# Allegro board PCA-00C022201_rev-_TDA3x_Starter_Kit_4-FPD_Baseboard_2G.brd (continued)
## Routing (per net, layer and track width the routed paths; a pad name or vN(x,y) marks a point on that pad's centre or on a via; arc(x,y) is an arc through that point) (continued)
RGMII1_RXCTL: length 17.3
  TOP w0.127: J14.132 v1(76.52,4.76) ; U48.7 v1(82.54,13.21)
  INNER1 w0.127: v1(76.52,4.76) 77.72,5.27 78.3,5.27 78.55,5.02 79.63,5.02 80.01,5.21 80.39,5.59 80.39,7.24 82.54,9.39 v1(82.54,13.21)
RGMII1_RXD0: length 17.2
  TOP w0.127: U48.3 v1(80.54,14.99) ; J14.143 v1(79.52,10.92)
  INNER1 w0.127: v1(79.52,10.92) 78.78,10.18 78.78,9.82 78.9,9.7 79.16,9.7 80.52,11.05 80.52,11.35 80.39,11.48 79.65,11.48 79.52,11.6 79.52,11.86 79.65,11.98 80.39,11.98 80.52,12.11 80.52,12.37 80.39,12.49 79.65,12.49 79.52,12.62 79.52,12.87 79.65,13 80.39,13 80.52,13.13 80.52,13.38 80.39,13.51 79.65,13.51 79.52,13.64 79.52,13.86 79.63,13.97 80.29,13.97 80.42,14.1 80.42,14.3 80.29,14.43 79.94,14.43 79.81,14.55 79.81,14.86 79.94,14.99 v1(80.54,14.99)
  BOTTOM w0.127: R205.2 79.89,14.99 v1(80.54,14.99)
RGMII1_RXD1: length 17.2
  TOP w0.127: U48.4 v1(81.04,15.75) ; v1(79.82,5.84) 79.02,5.04 J14.142
  INNER1 w0.127: v1(79.82,5.84) 79.31,5.33 78.8,5.33 78.23,5.91 78.23,6.48 78.97,7.21 78.97,8.86 81.04,10.93 v1(81.04,15.75)
  BOTTOM w0.127: R206.2 81.04,16.52 v1(81.04,15.75)
RGMII1_RXD2: length 17.2
  TOP w0.127: v1(79.44,8.51) 79.02,8.93 J14.141 ; U48.5 v1(81.54,14.99)
  INNER1 w0.127: v1(81.54,14.99) 82.04,14.99 82.3,15.24 82.61,15.24 82.74,15.11 82.74,14.86 81.54,13.66 81.54,10.8 81.28,10.55 81.28,10.37 81.55,10.1 81.55,9.92 81.37,9.74 81.19,9.74 80.92,10.01 80.75,10.01 80.57,9.83 80.57,9.65 80.96,9.25 80.96,9.08 80.78,8.9 80.6,8.9 80.21,9.29 80.03,9.29 79.85,9.11 79.85,8.93 80.24,8.54 80.24,8.36 79.76,7.87 79.54,7.87 79.44,7.97 v1(79.44,8.51)
  BOTTOM w0.127: R207.1 81.54,14.17 v1(81.54,14.99)
RGMII1_RXD3: length 17.2
  TOP w0.127: v1(79.06,5.84) 78.52,5.3 J14.140 ; U48.6 v1(82.04,15.75)
  INNER1 w0.127: v1(79.06,5.84) 79.88,6.67 79.88,7.37 82.04,9.52 82.04,13.52 83.82,15.3 83.82,15.81 83.5,16.13 82.42,16.13 v1(82.04,15.75)
RGMII1_TXC: length 40.5
  TOP w0.127: v1(82.17,33.02) 82.8,33.02 83.44,33.66 85.47,33.66 86.11,34.29 86.61,34.29 86.78,34.13 U9.29 ; J14.135 v1(77.52,8.7)
  INNER1 w0.127: v1(77.52,8.7) 77.52,13.29 77.09,13.72 77.09,16.45 79.88,19.24 79.88,19.65 79.45,20.09 79.45,20.27 79.63,20.44 79.81,20.44 80.36,19.89 80.54,19.89 80.72,20.07 80.72,20.25 79.78,21.19 79.78,21.36 79.96,21.54 80.14,21.54 81.08,20.61 81.26,20.61 81.44,20.79 81.44,20.97 80.5,21.9 80.5,22.08 80.68,22.26 80.86,22.26 81.64,21.49 81.82,21.49 82.17,21.84 v1(82.17,33.02)
RGMII1_TXCTL: length 40.5
  TOP w0.127: J14.138 v1(78.02,4.76) ; v1(86.36,29.53) 86.76,29.93 U9.37
  INNER1 w0.127: v1(86.36,29.53) 86.36,18.25 86.23,18.12 85.03,18.12 84.9,17.99 84.9,17.74 85.03,17.61 86.23,17.61 86.36,17.48 86.36,17.23 86.23,17.1 85.03,17.1 84.9,16.98 84.9,16.72 85.03,16.6 86.23,16.6 86.36,16.47 86.36,16.21 86.23,16.09 85.03,16.09 84.9,15.96 84.9,15.71 85.03,15.58 86.23,15.58 86.41,15.4 86.41,14.4 83.31,11.3 83.31,9.46 80.9,7.05 80.9,5.4 80.14,4.64 78.15,4.64 v1(78.02,4.76)
RGMII1_TXD0: length 40.4
  TOP w0.127: v1(81.53,34.16) 85.34,34.16 85.88,34.7 86.77,34.7 86.84,34.63 U9.28 ; v1(76.2,5.84) 77.02,5.02 J14.134
  INNER1 w0.127: v1(76.2,5.84) 76.2,7.87 74.68,9.4 74.68,17.91 81.03,24.26 81.03,33.66 v1(81.53,34.16)
RGMII1_TXD1: length 40.5
  TOP w0.127: v1(82.17,34.92) 82.68,35.43 85.6,35.43 85.91,35.13 U9.27 ; v1(77.03,5.84) 77.52,5.35 J14.136
  INNER1 w0.127: v1(82.17,34.92) 82.17,33.91 81.53,33.27 81.53,24 76.07,18.54 76.07,10.49 75.95,10.36 75.76,10.36 75.63,10.23 75.63,9.98 75.76,9.85 75.95,9.85 76.07,9.72 76.07,9.02 77.03,8.06 v1(77.03,5.84)
RGMII1_TXD2: length 40.5
  TOP w0.127: J14.137 v1(78.02,10.92) ; v1(82.8,36.32) 83.12,36.64 85.03,36.64 86.04,35.63 U9.26
  INNER1 w0.127: v1(78.02,10.92) 78.02,13.55 77.6,13.97 77.6,16.19 81.23,19.83 81.41,19.83 81.84,19.41 82.02,19.41 82.2,19.59 82.2,19.77 81.77,20.19 81.77,20.37 81.95,20.55 82.13,20.55 82.56,20.13 82.74,20.13 82.92,20.31 82.92,20.48 82.61,20.79 82.61,21.21 82.8,21.4 82.8,21.93 82.93,22.06 83.31,22.06 83.44,22.19 83.44,22.44 83.31,22.57 82.93,22.57 82.8,22.7 82.8,22.95 82.93,23.08 83.31,23.08 83.44,23.2 83.44,23.46 83.31,23.58 82.93,23.58 82.8,23.71 82.8,23.97 82.93,24.09 83.31,24.09 83.44,24.22 83.44,24.47 83.31,24.6 82.93,24.6 82.8,24.73 82.8,24.98 82.93,25.11 83.31,25.11 83.44,25.24 83.44,25.49 83.31,25.62 82.93,25.62 82.8,25.74 v1(82.8,36.32)
RGMII1_TXD3: length 40.5
  TOP w0.127: U9.25 86.3,36.13 85.22,37.21 v1(83.57,37.21) ; v1(78.52,11.56) J14.139
  INNER1 w0.127: v1(78.52,11.56) 78.52,13.81 78.11,14.22 78.11,15.94 78.99,16.82 79.17,16.82 79.47,16.53 79.65,16.53 79.82,16.71 79.82,16.89 79.53,17.18 79.53,17.36 79.71,17.54 79.89,17.54 80.18,17.25 80.36,17.25 80.54,17.42 80.54,17.6 80.25,17.9 80.25,18.08 80.45,18.29 83.06,18.29 84.2,19.43 84.2,25.65 83.57,26.29 83.57,29.14 83.69,29.27 83.82,29.27 83.95,29.39 83.95,29.65 83.82,29.77 83.69,29.77 83.57,29.9 83.57,30.16 83.69,30.28 83.82,30.28 83.95,30.41 83.95,30.66 83.82,30.79 83.69,30.79 83.57,30.92 83.57,31.17 83.69,31.3 83.82,31.3 83.95,31.43 83.95,31.68 83.82,31.81 83.69,31.81 83.57,31.93 83.57,32.19 83.69,32.31 83.82,32.31 83.95,32.44 83.95,32.7 83.82,32.82 83.69,32.82 83.57,32.95 83.57,33.2 83.69,33.33 83.82,33.33 83.95,33.46 83.95,33.71 83.82,33.84 83.69,33.84 83.57,33.97 v1(83.57,37.21)
RIN0_C_N: length 14
  BOTTOM w0.127: R67.2 6.67,16.83 C77.2 7.68,16.36 7.81,16.23 10.13,16.23 11.35,17.45 15.39,17.45 15.61,17.67 L19.1 L19.2 17.92,17.67 18.14,17.45 18.82,17.45 C75.1
RIN0_C_P: length 19.5
  TOP w0.127: J6.5 v1(3.68,15.88)
  BOTTOM w0.127: C73.1 18.82,17.09 18.14,17.09 17.92,16.87 L19.3 L19.4 15.61,16.87 15.39,17.09 11.5,17.09 10.28,15.88 v1(3.68,15.88)
  BOTTOM w0.381: L17.2 4.36,16.55 v1(3.68,15.88)
RIN0_N: length 11.3
  BOTTOM w0.127: C75.2 20.6,17.45 22.66,17.45 27.74,22.53 29.13,22.53 U6.51
RIN0_P: length 11.3
  BOTTOM w0.127: C73.2 20.6,17.09 22.81,17.09 27.89,22.17 29.13,22.17 U6.50
RIN1_C_N: length 14
  BOTTOM w0.127: C76.1 18.82,30.15 18.14,30.15 17.92,30.37 L20.2 L20.1 15.61,30.37 15.39,30.15 11.35,30.15 10.13,28.93 7.81,28.93 7.68,29.06 C78.2 6.67,29.53 R68.2
RIN1_C_P: length 19.5
  TOP w0.127: J7.5 v1(3.68,28.57)
  BOTTOM w0.127: C74.1 18.82,29.79 18.14,29.79 17.92,29.57 L20.3 L20.4 15.61,29.57 15.39,29.79 11.5,29.79 10.28,28.57 v1(3.68,28.57)
  BOTTOM w0.381: L18.2 4.36,29.25 v1(3.68,28.57)
RIN1_N: length 12.1
  BOTTOM w0.127: C76.2 20.6,30.15 21.29,30.15 22.23,29.21 22.23,28.57 26.77,24.03 29.13,24.03 U6.54
RIN1_P: length 12.1
  BOTTOM w0.127: U6.53 29.13,23.67 26.63,23.67 21.87,28.43 21.87,29.06 21.14,29.79 20.6,29.79 C74.2
RIN2_C_N: length 14
  BOTTOM w0.127: R75.2 6.67,42.23 C91.2 7.68,41.76 7.81,41.63 10.13,41.63 11.35,42.85 15.39,42.85 15.61,43.07 L29.1 L29.2 17.92,43.07 18.14,42.85 18.82,42.85 C89.1
RIN2_C_P: length 19.5
  TOP w0.127: J8.5 v1(3.68,41.27)
  BOTTOM w0.127: v1(3.68,41.27) 10.28,41.27 11.5,42.49 15.39,42.49 15.61,42.27 L29.4 L29.3 17.92,42.27 18.14,42.49 18.82,42.49 C87.1
  BOTTOM w0.381: L27.2 4.36,41.95 v1(3.68,41.27)
RIN2_N: length 21.3
  BOTTOM w0.127: C89.2 20.6,42.85 21.67,42.85 26.8,37.72 26.8,28.19 27.96,27.03 29.13,27.03 U6.60
RIN2_P: length 21.3
  BOTTOM w0.127: U6.59 29.13,26.67 27.82,26.67 26.44,28.05 26.44,37.57 21.52,42.49 20.6,42.49 C87.2
RIN3_C_N: length 14
  BOTTOM w0.127: R76.2 6.67,54.93 C92.2 7.68,54.46 7.81,54.33 10.13,54.33 11.35,55.55 15.39,55.55 15.61,55.77 L30.1 L30.2 17.92,55.77 18.14,55.55 18.82,55.55 C90.1
RIN3_C_P: length 19.5
  TOP w0.127: J9.5 v1(3.68,53.98)
  BOTTOM w0.127: C88.1 18.82,55.19 18.14,55.19 17.92,54.97 L30.3 L30.4 15.61,54.97 15.39,55.19 11.5,55.19 10.28,53.98 v1(3.68,53.98)
  BOTTOM w0.381: L28.2 4.36,54.65 v1(3.68,53.98)
RIN3_N: length 32.5
  BOTTOM w0.127: U6.63 29.13,28.53 28.19,28.53 27.88,28.84 27.88,29.53 28.04,29.69 28.04,38.76 27.05,39.75 27.05,50.16 21.67,55.55 20.6,55.55 C90.2
RIN3_P: length 32.5
  BOTTOM w0.127: U6.62 29.13,28.17 28.04,28.17 27.52,28.69 27.52,29.68 27.69,29.84 27.69,38.61 26.7,39.6 26.7,50.02 21.52,55.19 20.6,55.19 C88.2
RSTOUTN: length 65.6
  TOP w0.152: TP78.1 89.41,1.65 89.15,1.91 86.02,1.91 ; 86.02,1.91 85,0.89 33.78,0.89 31.37,3.3 29.84,3.3 29.07,4.07 U22.3 ; 86.02,1.91 J14.170
RTCK: length 47.7
  TOP w0.127: J14.179 v1(88.52,10.73)
  INNER2 w0.127: v1(63.39,21.18) 63.39,18.53 73.15,8.76 75.18,8.76 81.92,2.03 87.38,2.03 89.03,3.68 89.03,5.97 86.98,8.01 86.98,9.19 v1(88.52,10.73)
  BOTTOM w0.127: v1(63.39,21.18) 62.89,21.68 J13.7
RX_CLK: length 2.4
  TOP w0.127: R179.2 85.72,32.77 86.04,32.45 86.68,32.45 86.85,32.63 U9.32
RX_CTRL: length 2.4
  TOP w0.127: R174.2 87.76,28.45 88.56,29.25 U9.38
RX_D0: length 2.4
  TOP w0.127: U9.33 86.29,32.13 85.83,31.66 RN5.8
RX_D1: length 2.4
  TOP w0.127: U9.34 86.36,31.63 85.85,31.11 RN5.7
RX_D2: length 2.4
  TOP w0.127: RN5.6 85.98,30.61 86.5,31.13 U9.35
RX_D3: length 2.4
  TOP w0.127: U9.36 86.63,30.63 86.07,30.06 RN5.5
SD_DETECT: length 121.2
  TOP w0.152: U22.18 v1(23.41,6.68)
  INNER1 w0.152: v1(23.41,6.68) 22.73,6 22.73,3.56 24,2.29 25.27,2.29 25.78,2.79 28.32,2.79 28.96,2.16 30.35,2.16 31.11,2.92 48.39,2.92 50.04,4.57 51.69,4.57 53.85,6.73 56.52,6.73 63.25,13.46 67.5,13.46 76.83,22.8 76.83,32 86.11,41.27 88.9,41.27 89.41,41.78 94.74,41.78 96.52,43.56 96.52,55.31 95.76,56.07 v1(91.18,56.07)
  BOTTOM w0.152: R151.2 R158.2 v1(91.18,56.07)
SPI1_CS1/SPI3_CS1: length 85.5
  TOP w0.127: J14.162 v1(84.02,4.76)
  INNER2 w0.127: v1(69.22,49.47) 68.45,50.23 59.82,50.23 59.05,49.47 51.88,49.47 45.59,55.75 41.15,55.75 J27.10
  BOTTOM w0.127: v1(69.22,49.47) 69.22,35.05 73.28,30.99 73.28,17.46 78.42,12.32 79.12,12.32 84.02,7.42 v1(84.02,4.76)
SW_RX_CLK: length 14.5
  TOP w0.127: R179.1 83.63,32.77 80.54,29.67 U48.18
SW_RX_CTRL: length 14.5
  TOP w0.127: U48.13 83.04,21.32 84.33,22.61 84.33,23.08 84.45,23.21 84.8,23.21 84.92,23.33 84.92,23.59 84.8,23.72 84.45,23.72 84.33,23.84 84.33,24.1 84.45,24.22 84.8,24.22 84.92,24.35 84.92,24.6 84.8,24.73 84.45,24.73 84.33,24.86 84.33,26.92 83.82,27.43 83.82,28.96 84.14,29.27 85.15,29.27 85.41,29.02 85.41,28.64 85.6,28.45 R174.1
SW_RX_D0: length 14.4
  TOP w0.127: U48.17 81.04,22.66 81.16,22.79 81.28,22.79 81.41,22.92 81.41,23.17 81.28,23.3 81.16,23.3 81.04,23.42 81.04,23.68 81.16,23.8 81.28,23.8 81.41,23.93 81.41,24.19 81.28,24.31 81.16,24.31 81.04,24.44 81.04,29.48 83.22,31.66 RN5.1
SW_RX_D1: length 14.5
  TOP w0.127: U48.16 81.54,22.1 81.92,22.48 81.92,24.66 81.79,24.79 81.66,24.79 81.53,24.92 81.53,25.17 81.66,25.3 81.79,25.3 81.92,25.42 81.92,25.68 81.79,25.81 81.66,25.81 81.53,25.93 81.53,26.19 81.66,26.31 81.79,26.31 81.92,26.44 81.92,26.69 81.79,26.82 81.66,26.82 81.53,26.95 81.53,27.2 81.66,27.33 81.79,27.33 81.92,27.46 81.92,27.71 81.79,27.84 81.66,27.84 81.53,27.96 81.53,29.27 83.37,31.11 RN5.2
SW_RX_D2: length 14.6
  TOP w0.127: U48.15 82.04,21.84 82.42,22.23 82.42,23.12 82.55,23.25 82.68,23.25 82.8,23.38 82.8,23.63 82.68,23.76 82.55,23.76 82.42,23.89 82.42,24.14 82.55,24.27 82.68,24.27 82.8,24.39 82.8,24.65 82.68,24.77 82.55,24.77 82.42,24.9 82.42,25.16 82.55,25.28 82.68,25.28 82.8,25.41 82.8,25.66 82.68,25.79 82.55,25.79 82.42,25.92 82.42,26.17 82.55,26.3 82.68,26.3 82.8,26.43 82.8,26.68 82.68,26.81 82.55,26.81 82.42,26.93 82.42,27.19 82.55,27.31 82.68,27.31 82.8,27.44 82.8,27.7 82.68,27.82 82.55,27.82 82.42,27.95 82.42,28.32 82.3,28.45 82.17,28.45 82.04,28.58 82.04,29.02 83.63,30.61 RN5.3
SW_RX_D3: length 14.5
  TOP w0.127: RN5.4 83.78,30.06 83.31,29.59 83.31,29.19 83.19,29.07 82.96,29.07 82.83,28.94 82.83,28.69 82.96,28.56 83.19,28.56 83.31,28.43 83.31,26.91 83.44,26.78 83.69,26.78 83.82,26.65 83.82,26.4 83.69,26.27 83.44,26.27 83.31,26.15 83.31,25.89 83.44,25.76 83.69,25.76 83.82,25.64 83.82,25.38 83.69,25.26 83.44,25.26 83.31,25.13 83.31,24.88 83.44,24.75 83.69,24.75 83.82,24.62 83.82,24.37 83.69,24.24 83.44,24.24 83.31,24.11 83.31,23.86 83.44,23.73 83.69,23.73 83.82,23.61 83.82,23.35 83.69,23.22 83.49,23.22 83.31,23.05 83.31,22.35 82.54,21.58 U48.14
TCLK: length 37.2
  TOP w0.127: J14.180 v1(88.52,4.76)
  INNER2 w0.127: v1(64.39,21.18) 64.39,19.05 73.66,9.78 77.34,9.78 80.84,6.29 80.84,4.89 81.79,3.94 87.69,3.94 v1(88.52,4.76)
  BOTTOM w0.127: J13.3 63.89,21.68 v1(64.39,21.18)
TD_A_N: length 12.9
  TOP w0.127: U9.2 94.33,31.05 95.3,31.05 95.63,30.72 95.63,29.97 95.35,29.69 95.35,29.36 95.51,29.2 96.19,29.2 96.31,29.32 96.31,30.08 96.65,30.42 97.09,30.42 v1(97.24,30.57)
  BOTTOM w0.127: J24.10 102.11,30.1 101.9,29.89 101.09,29.89 100.97,30.02 100.97,30.78 100.63,31.11 98.87,31.11 98.18,30.42 97.4,30.42 v1(97.24,30.57)
TD_A_P: length 12.9
  TOP w0.127: U9.1 94.33,30.7 95.15,30.7 95.28,30.57 95.28,30.12 95,29.84 95,29.21 95.37,28.84 96.33,28.84 96.67,29.18 96.67,29.94 96.8,30.06 97.09,30.06 v1(97.24,29.91)
  BOTTOM w0.127: J24.11 102.11,29.34 101.91,29.54 100.94,29.54 100.61,29.87 100.61,30.63 100.48,30.76 99.02,30.76 98.33,30.06 97.4,30.06 v1(97.24,29.91)
TD_B_N: length 12.9
  TOP w0.127: v1(98.22,31.71) 98.07,31.86 98.07,32.2 97.72,32.55 94.33,32.55 U9.5
  BOTTOM w0.127: J24.5 104.65,30.23 104.32,30.56 103.86,30.56 102.54,31.88 99.19,31.88 98.89,32.18 98.2,32.18 98.07,32.05 98.07,31.86 v1(98.22,31.71)
TD_B_P: length 12.9
  TOP w0.127: v1(97.56,31.71) 97.72,31.86 97.72,32.06 97.58,32.2 94.33,32.2 U9.4
  BOTTOM w0.127: J24.4 104.65,31.24 104.32,30.91 104.01,30.91 102.69,32.23 99.34,32.23 99.03,32.54 98.05,32.54 97.72,32.2 97.72,31.86 v1(97.56,31.71)
TD_C_N: length 12.9
  TOP w0.127: U9.8 94.33,34.05 97.32,34.05 v1(97.47,34.21)
  BOTTOM w0.127: J24.2 104.65,35.24 104.38,34.97 103.52,34.97 103.19,34.64 103.19,33.63 103.06,33.5 101.67,33.5 101.39,33.78 100.6,33.78 100.32,33.5 99.85,33.5 99.3,34.05 97.62,34.05 v1(97.47,34.21)
TD_C_P: length 12.9
  TOP w0.127: v1(97.47,33.55) 97.32,33.7 94.33,33.7 U9.7
  BOTTOM w0.127: v1(97.47,33.55) 97.62,33.7 99.15,33.7 99.7,33.15 100.47,33.15 100.75,33.43 101.24,33.43 101.52,33.15 103.21,33.15 103.54,33.48 103.54,34.49 103.67,34.62 104.38,34.62 104.65,34.35 J24.3
TD_D_N: length 12.9
  TOP w0.127: v1(97.55,36.07) 97.71,35.92 97.71,35.35 97.58,35.22 97.03,35.22 96.9,35.34 96.9,36.22 96.57,36.55 95.91,36.55 95.57,36.22 95.57,35.68 95.45,35.55 94.33,35.55 U9.11
  BOTTOM w0.127: v1(97.55,36.07) 97.71,35.92 97.71,35.41 98.04,35.08 98.53,35.08 98.87,34.73 100.67,34.73 101,35.07 101,35.51 101.13,35.64 101.9,35.64 102.11,35.43 J24.9
TD_D_P: length 12.9
  TOP w0.127: U9.10 94.33,35.2 95.59,35.2 95.93,35.53 95.93,36.07 96.06,36.2 96.42,36.2 96.55,36.07 96.55,35.2 96.88,34.86 97.73,34.86 98.06,35.2 98.06,35.92 v1(98.21,36.07)
  BOTTOM w0.127: v1(98.21,36.07) 98.06,35.92 98.06,35.56 98.19,35.43 98.68,35.43 99.02,35.09 100.52,35.09 100.65,35.22 100.65,35.66 100.98,35.99 101.91,35.99 102.11,36.2 J24.8
TDI: length 36.7
  TOP w0.127: J14.174 v1(87.02,2.54)
  INNER2 w0.127: v1(87.02,2.54) 82.42,2.54 80.39,4.57 80.39,6.1 79.63,6.86 77.85,6.86 75.44,9.27 73.41,9.27 63.87,18.81 63.87,21.42 v1(63.39,21.89)
  BOTTOM w0.127: J13.5 v1(63.39,21.89)
TDO: length 40.6
  TOP w0.127: J14.176 v1(87.52,4.76)
  INNER2 w0.127: v1(87.52,4.76) 87.2,4.45 86.11,4.45 85.34,5.21 85.34,5.46 80.52,10.29 73.91,10.29 64.95,19.25 64.95,25.73 v1(63.63,27.05)
  BOTTOM w0.127: v1(63.63,27.05) 63.89,27.31 J13.4
TFP410_DKEN: length 2.3
  TOP w0.127: R137.2 100.75,58.71 100.25,58.21 U16.35
TFP410_HTPLG: length 2.7
  TOP w0.127: U16.9 97.75,44.79 v1(97.28,44.32)
  BOTTOM w0.127: R136.2 97.03,44.58 v1(97.28,44.32)
TFP410_MSEN: length 2.3
  TOP w0.127: R138.2 98.75,43.38 U16.11
TFP410_PDN: length 99.7
  TOP w0.127: U22.20 v1(23.37,5.37)
  INNER1 w0.127: v1(93.73,42.86) 93.19,42.32 89.19,42.32 88.65,41.78 85.98,41.78 76.33,32.13 76.33,22.99 67.25,13.91 63.06,13.91 56.39,7.24 53.59,7.24 51.44,5.08 49.85,5.08 48.13,3.37 29.02,3.37 28.32,4.06 26.29,4.06 25.02,2.79 24.26,2.79 23.37,3.68 v1(23.37,5.37)
  BOTTOM w0.127: v1(93.73,42.86) 95.95,42.86 96.33,43.24 R134.2
TFP410_TFADJ: length 2.8
  TOP w0.127: v1(105.16,48.9) 104.39,48.9 104.18,48.68 103.25,48.68
  BOTTOM w0.127: v1(105.16,48.9) R139.1
TMS: length 37.1
  TOP w0.127: v1(88.02,5.52) J14.178
  INNER2 w0.127: v1(64.39,27.64) 64.39,27.18 85.89,5.67 85.89,5.29 86.23,4.95 86.8,4.95 87.38,5.52 v1(88.02,5.52)
  BOTTOM w0.127: J13.2 v1(64.39,27.64)
TRSTN: length 56.7
  TOP w0.127: R110.2 61.65,26.84 v1(61.65,27.56) 61.65,28.34 R109.2 ; J14.177 88.02,8.88 v1(88.42,8.48)
  INNER2 w0.127: v1(61.65,27.56) 60.38,26.29 60.38,24.7 62.47,22.61 62.47,17.92 73.66,6.73 73.66,4.7 76.14,2.22 76.14,1.52 76.52,1.14 87.76,1.14 89.79,3.17 89.79,6.48 88.42,7.85 v1(88.42,8.48)
TRSTPD: length 3.5
  TOP w0.127: R111.1 R109.1 62.63,27.89 v1(62.89,27.62)
  BOTTOM w0.127: J13.8 v1(62.89,27.62)
TVDD: length 2.3
  TOP w0.203: 103.25,53.68 v1(104.4,53.68) ; 103.25,50.68 v1(104.39,50.68)
TVDD_HDMI_IN: length 3.5
  TOP w0.305: U44.5 v1(57.25,50.04) ; U44.11 v1(54.25,50.04) ; U44.8 v1(55.75,50.04)
TXC_N: length 18.4
  TOP w0.127: 103.25,49.68 103.32,49.75 105.88,49.75 108.11,51.98 108.7,51.98 109.02,51.66 U20.15 111.03,51.66 111.36,51.98 114.2,51.98 114.52,51.66 U20.24 116.53,51.66 116.85,51.98 118.4,51.98 118.85,52.43 119.97,52.43 J19.12
TXC_P: length 18.4
  TOP w0.127: 103.25,50.18 103.32,50.11 105.74,50.11 107.97,52.34 108.7,52.34 109.02,52.66 U20.13 111.03,52.66 111.36,52.34 114.2,52.34 114.52,52.66 U20.26 116.53,52.66 116.85,52.34 118.25,52.34 118.7,52.79 119.97,52.79 J19.11
TXD0_N: length 18.4
  TOP w0.127: 103.25,51.18 103.32,51.25 105.48,51.25 107.71,53.49 108.7,53.49 109.02,53.16 U20.12 111.03,53.16 111.36,53.49 114.2,53.49 114.52,53.16 U20.27 116.53,53.16 116.85,53.49 117.21,53.49 117.35,53.34 118.23,53.34 118.53,53.63 119.97,53.63 J19.9
TXD0_P: length 18.4
  TOP w0.127: 103.25,51.68 103.32,51.61 105.33,51.61 107.56,53.84 108.7,53.84 109.02,54.16 U20.10 111.03,54.16 111.36,53.84 114.2,53.84 114.52,54.16 U20.29 116.53,54.16 116.85,53.84 117.36,53.84 117.5,53.7 118.08,53.7 118.38,53.99 119.97,53.99 J19.8
TXD1_N: length 18.4
  TOP w0.127: J19.6 119.97,54.84 118.52,54.84 118.22,55.13 117.48,55.13 117.34,54.99 116.85,54.99 116.53,54.66 U20.30 114.52,54.66 114.2,54.99 111.36,54.99 111.03,54.66 U20.9 109.02,54.66 108.7,54.99 107.3,54.99 105.07,52.75 103.32,52.75 103.25,52.68
TXD1_P: length 18.4
  TOP w0.127: J19.5 119.97,55.19 118.67,55.19 118.37,55.49 117.34,55.49 117.19,55.34 116.85,55.34 116.53,55.66 U20.32 114.52,55.66 114.2,55.34 111.36,55.34 111.03,55.66 U20.7 109.02,55.66 108.7,55.34 107.16,55.34 104.93,53.11 103.32,53.11 103.25,53.18
TXD2_N: length 18.4
  TOP w0.127: 103.25,54.18 103.32,54.25 104.67,54.25 106.9,56.49 108.7,56.49 109.02,56.16 U20.6 111.03,56.16 111.36,56.49 114.2,56.49 114.52,56.16 U20.33 116.53,56.16 116.85,56.49 118.52,56.49 118.97,56.03 119.97,56.03 J19.3
TXD2_P: length 18.4
  TOP w0.127: J19.2 119.97,56.39 119.12,56.39 118.67,56.84 116.85,56.84 116.53,57.16 U20.35 114.52,57.16 114.2,56.84 111.36,56.84 111.03,57.16 U20.4 109.02,57.16 108.7,56.84 106.75,56.84 104.52,54.61 103.32,54.61 103.25,54.68
UART1_RXD/DCAN2_TX: length 85.1
  TOP w0.127: J14.117 68.02,8.95 68.83,8.13 v1(69.72,8.13)
  INNER1 w0.127: v1(45.59,52.2) 46.86,53.47 46.86,60.96 43.56,64.26 42.8,64.26 J27.3
  BOTTOM w0.127: v1(45.59,52.2) 46.35,51.44 46.35,40.77 44.83,39.24 44.83,35.69 46.99,33.53 66.17,33.53 70.17,29.53 70.17,8.57 v1(69.72,8.13)
UART1_TXD/DCAN2_RX: length 80.9
  TOP w0.127: J14.119 68.92,9.82 v1(70.61,8.13)
  INNER1 w0.127: v1(45.59,53.09) 45.59,58.93 J27.5
  BOTTOM w0.127: v1(45.59,53.09) 46.86,51.82 46.86,40.51 45.34,38.99 45.34,35.94 47.24,34.04 66.42,34.04 70.61,29.84 v1(70.61,8.13)
UART2_CTSN: length 116.9
  TOP w0.152: v1(67.31,2.48) 67.02,2.77 J14.114
  INNER2 w0.152: J27.6 36.7,58.93 36.7,47.62 39.5,44.83 39.5,40.77 41.27,38.99 41.27,33.78 44.7,30.35 44.7,16 51.94,8.76 51.94,3.68 53.09,2.54 63.88,2.54 64.77,1.65 66.48,1.65 v1(67.31,2.48)
  BOTTOM w0.152: v1(67.31,2.48) 67.88,1.91 69.09,1.91 69.85,2.67 86.11,2.67 87,3.56 91.44,3.56 92.84,2.16 R324.1 98.86,2.16 Q7.1
UART2_RTSN: length 114
  TOP w0.152: J14.112 v1(66.52,2.54)
  INNER2 w0.152: J27.8 37.97,57.66 37.97,48.13 41.66,44.45 41.66,39.5 41.91,39.24 41.91,35.98 45.15,32.75 45.15,19.11 52.45,11.81 52.45,3.94 53.34,3.05 64.07,3.05 65.09,2.03 66.01,2.03 v1(66.52,2.54)
  BOTTOM w0.152: v1(66.52,2.54) 67.15,3.17 85.85,3.17 86.74,4.06 91.69,4.06 92.84,2.92 R323.1 95.25,3.05 95.89,3.68 96.27,3.68 96.9,4.32 96.9,4.95 97.16,5.21 98.68,5.21 98.86,5.39 Q8.1
UART2_RXD: length 90.9
  TOP w0.152: v1(71.37,5.78) 70.68,5.08 68.45,5.08 68.02,4.64 J14.118
  INNER1 w0.152: J27.4 41.15,63.37 43.31,63.37 46.23,60.45 v1(46.23,53.85)
  BOTTOM w0.152: v1(71.37,5.78) 71.75,6.16 71.75,30.23 66.93,35.05 47.75,35.05 47.12,35.69 47.12,38.48 47.88,39.24 47.88,53.47 47.5,53.85 v1(46.23,53.85)
UART2_TXD: length 92.9
  TOP w0.152: v1(70.36,5.78) 68.39,5.78 67.52,4.91 J14.116
  INNER1 w0.152: v1(47.37,53.09) 47.37,61.72 43.18,65.91 41.15,65.91 J27.2
  BOTTOM w0.152: v1(70.36,5.78) 71.25,6.68 71.25,29.96 66.67,34.54 47.5,34.54 45.85,36.2 45.85,38.61 47.37,40.13 v1(47.37,53.09)
UART3_CTSN: length 90.4
  TOP w0.152: v1(45.34,45.21) 41.78,45.21 39.69,43.12 v1(34.61,43.12) ; J14.164 v1(84.52,5.46)
  INNER2 w0.152: v1(69.85,48.13) 66.8,45.09 63.37,45.09 61.66,46.8 55.37,46.8 54.61,46.04 50.74,46.04 49.91,45.21 v1(45.34,45.21)
  BOTTOM w0.152: v1(69.85,48.13) 69.85,35.18 73.79,31.24 73.79,17.72 78.68,12.83 79.38,12.83 84.52,7.68 v1(84.52,5.46) ; R104.2 v1(34.61,43.12)
UART3_RTSN: length 93.9
  TOP w0.152: J14.166 v1(85.02,4.76) ; v1(32.32,43.12) 34.29,45.09 37.01,45.09 39.29,47.37 v1(45.34,47.37)
  INNER2 w0.152: v1(70.48,48.77) 67.69,48.77 67.12,49.34 60.33,49.34 59.44,48.45 50.99,48.45 49.91,47.37 v1(45.34,47.37)
  BOTTOM w0.152: v1(70.48,48.77) 70.48,35.31 74.3,31.5 74.3,17.97 78.93,13.34 80.77,13.34 85.02,9.09 v1(85.02,4.76) ; R101.2 v1(32.32,43.12)
UART3_RXD_BOOT: length 90.7
  TOP w0.152: v1(36.51,43.81) 39.49,43.81 41.53,45.85 46.1,45.85 v1(48.51,48.26) ; J14.158 v1(83.02,4.76)
  INNER2 w0.152: v1(48.51,48.26) 49.91,48.26 50.61,48.96 59.25,48.96 60.07,49.78 67.63,49.78 v1(67.94,49.47)
  BOTTOM w0.152: v1(67.94,49.47) 67.94,34.8 72.26,30.48 72.26,11.18 73.91,9.53 80.39,9.53 83.02,6.9 v1(83.02,4.76) ; R105.2 v1(36.51,43.81)
UART3_TXD_BOOT: length 92.4
  TOP w0.152: v1(83.52,5.46) J14.160 ; v1(45.34,46.48) 41.15,46.48 39.12,44.45 34.8,44.45 v1(33.46,43.12)
  INNER2 w0.152: v1(68.58,48.13) 64.52,48.13 64.33,47.94 51.37,47.94 49.91,46.48 v1(45.34,46.48)
  BOTTOM w0.152: v1(68.58,48.13) 68.58,34.93 72.77,30.73 72.77,11.43 74.04,10.16 80.52,10.16 83.52,7.16 v1(83.52,5.46) ; R102.2 v1(33.46,43.12)
USB_CTS: length 1.3
  TOP w0.152: U47.15 33.14,54.3 R299.1
USB_DM: length 17
  TOP w0.135: J23.2 22.31,65.54 22.31,63.3 v1(22.5,63.11) ; v1(31.55,60.58) 31.74,60.39 31.74,59.44 31.63,59.33 U47.5
  BOTTOM w0.135: v1(31.55,60.58) 31.74,60.77 31.74,61.13 30.92,61.95 28.39,61.95 U49.5 28.15,61.95 27.64,61.95 27.15,62.43 26.79,62.43 U49.2 26.59,62.43 25.68,62.43 24.05,64.06 22.71,64.06 22.31,63.66 22.31,63.3 v1(22.5,63.11)
USB_DP: length 17.9
  TOP w0.135: U47.4 32.14,59.33 32.03,59.44 32.03,60.39 v1(32.22,60.58) ; v1(21.84,63.11) 22.03,63.3 22.03,65.54 J23.3
  BOTTOM w0.135: v1(32.22,60.58) 32.03,60.77 32.03,61.25 31.04,62.24 27.75,62.24 27.27,62.72 26.78,62.72 26.69,62.81 U49.3 26.58,62.72 25.8,62.72 24.17,64.35 22.59,64.35 22.03,63.78 22.03,63.3 v1(21.84,63.11)
USB_RTS: length 1.9
  TOP w0.152: R300.1 34.28,55.26 U47.16
USB_RXD: length 7.7
  TOP w0.152: v1(33.79,51.5) 34.29,51.5 35.18,52.39 35.18,55.75 34.53,56.4 U47.17
  BOTTOM w0.152: U38.11 v1(33.79,51.5)
USB_TXD: length 8.5
  TOP w0.152: U47.18 34.79,56.9 35.81,55.88 v1(35.81,52.07)
  BOTTOM w0.152: v1(35.81,52.07) 35.18,52.07 34.79,51.68 U38.13
VOUT1_CLK: length 98
  TOP w0.127: J14.51 v1(46.51,10.86) ; v1(90.49,51.18) 91.75,51.18 U16.57
  INNER1 w0.127: v1(46.51,10.86) 46.66,11.23 50.29,14.86 55.24,14.86 61.52,21.13 61.7,21.13 62.79,20.04 62.97,20.04 63.15,20.22 63.15,20.4 62.06,21.49 62.06,21.67 62.24,21.85 62.49,21.85 62.72,22.08 62.72,22.34 63.63,23.25 63.81,23.25 65.16,21.9 65.34,21.9 65.52,22.08 65.52,22.26 64.17,23.61 64.17,23.79 64.35,23.96 64.53,23.96 65.87,22.62 66.05,22.62 66.23,22.8 66.23,22.98 64.89,24.32 64.89,24.5 65.07,24.68 65.25,24.68 66.59,23.34 66.77,23.34 66.95,23.52 66.95,23.7 65.61,25.04 65.61,25.22 65.79,25.4 65.97,25.4 67.31,24.06 67.49,24.06 67.67,24.24 67.67,24.42 66.33,25.76 66.33,25.94 66.51,26.12 66.69,26.12 68.03,24.78 68.21,24.78 68.39,24.96 68.39,25.14 67.05,26.48 67.05,26.66 67.23,26.84 67.41,26.84 68.75,25.5 68.93,25.5 69.11,25.68 69.11,25.86 67.77,27.2 67.77,27.38 67.94,27.56 68.12,27.56 69.09,26.6 69.27,26.6 69.45,26.78 69.45,26.95 68.48,27.92 68.48,28.1 68.71,28.32 68.71,28.66 68.83,28.78 69.34,28.78 69.47,28.91 69.47,29.17 69.34,29.29 68.83,29.29 68.71,29.42 68.71,29.67 68.83,29.8 69.34,29.8 69.47,29.93 69.47,30.18 69.34,30.31 68.83,30.31 68.71,30.44 68.71,30.99 88.9,51.18 89.27,51.18 89.4,51.31 89.4,51.44 89.53,51.56 89.78,51.56 89.91,51.44 89.91,51.31 90.03,51.18 v1(90.49,51.18)
VOUT1_D0: length 93.5
  TOP w0.127: v1(90.49,48.18) U16.63 ; J14.43 44.51,8.95 44.7,8.76 49.34,8.76 50.48,7.62 v1(50.48,7.56)
  INNER1 w0.127: v1(90.49,48.18) 91.19,48.88 91.19,54.86 91.44,55.12 93.15,55.12 93.41,54.86 93.41,46.74 92.58,45.91 87.57,45.91 73.72,32.07 73.72,24.83 72.9,24 72.9,23.37 66.1,16.57 61.91,16.57 57.4,12.06 57.02,12.06 56.52,12.57 51.05,12.57 49.97,11.49 49.97,8.06 v1(50.48,7.56)
VOUT1_D1: length 93.9
  TOP w0.127: J14.41 44.01,8.82 44.37,8.46 48.69,8.46 v1(49.59,7.56) ; v1(89.66,48.68) U16.62
  INNER1 w0.127: v1(89.66,48.68) 89.66,48.13 90.11,47.69 90.87,47.69 91.63,48.45 91.63,54.42 91.82,54.61 92.77,54.61 92.96,54.42 92.96,47.18 92.14,46.35 87.33,46.35 73.28,32.3 73.28,25.02 72.39,24.13 72.39,23.5 65.91,17.02 61.72,17.02 57.4,12.7 57.02,12.7 56.77,12.95 50.93,12.95 49.59,11.62 v1(49.59,7.56)
VOUT1_D2: length 95.7
  TOP w0.127: v1(90.49,49.18) U16.61 ; v1(48.7,7.56) 48.11,8.15 44.09,8.15 43.51,8.73 J14.39
  INNER1 w0.127: v1(48.7,7.56) 49.15,8 49.15,11.68 50.8,13.34 57.4,13.34 61.53,17.46 65.09,17.46 65.45,17.83 65.63,17.83 65.77,17.69 65.95,17.69 66.13,17.87 66.13,18.05 65.99,18.19 65.99,18.37 66.17,18.55 66.35,18.55 66.49,18.41 66.67,18.41 66.85,18.59 66.85,18.77 66.71,18.91 66.71,19.09 66.89,19.27 67.07,19.27 67.21,19.13 67.39,19.13 67.57,19.31 67.57,19.49 67.43,19.63 67.43,19.81 67.61,19.99 67.79,19.99 67.93,19.85 68.11,19.85 68.29,20.03 68.29,20.21 68.15,20.35 68.15,20.53 68.33,20.7 68.51,20.7 68.65,20.57 68.83,20.57 69.01,20.75 69.01,20.93 68.87,21.06 68.87,21.24 69.05,21.42 69.23,21.42 69.37,21.29 69.55,21.29 69.73,21.47 69.73,21.65 69.59,21.78 69.59,21.96 69.77,22.14 69.95,22.14 70.08,22 70.26,22 70.44,22.18 70.44,22.36 70.31,22.5 70.31,22.68 70.49,22.86 70.67,22.86 70.8,22.72 70.98,22.72 71.16,22.9 71.16,23.08 71.03,23.22 71.03,23.4 71.21,23.58 71.38,23.58 71.52,23.44 71.7,23.44 71.88,23.62 71.88,23.8 71.74,23.94 71.74,24.12 72.83,25.21 72.83,32.58 87.06,46.8 91.63,46.8 92.52,47.69 92.52,52.32 92.39,52.45 92.2,52.45 92.08,52.32 92.08,48.2 91.12,47.24 89.92,47.24 89.09,48.07 89.09,48.83 89.44,49.18 v1(90.49,49.18)
VOUT1_D3: length 92.1
  TOP w0.127: v1(47.82,7.56) 47.52,7.85 43.84,7.85 43.01,8.68 J14.37 ; v1(89.66,49.68) U16.60
  INNER1 w0.127: v1(47.82,7.56) 48.64,8.38 48.64,11.68 50.67,13.72 57.15,13.72 61.34,17.91 62.01,17.91 62.14,18.03 62.14,18.54 62.26,18.67 62.52,18.67 62.64,18.54 62.64,18.03 62.77,17.91 63.02,17.91 63.15,18.03 63.15,18.54 63.28,18.67 63.53,18.67 63.66,18.54 63.66,18.03 63.79,17.91 64.14,17.91 64.32,18.09 64.32,18.27 64.21,18.37 64.21,18.55 64.39,18.73 64.57,18.73 65.06,18.25 65.24,18.25 65.51,18.52 65.51,18.7 65.37,18.83 65.37,19.01 65.56,19.2 65.74,19.2 65.87,19.06 66.05,19.06 66.23,19.24 66.23,19.42 66.1,19.56 66.1,19.74 66.28,19.92 66.46,19.92 66.59,19.78 66.77,19.78 66.95,19.96 66.95,20.14 66.81,20.28 66.81,20.46 66.99,20.64 67.17,20.64 67.31,20.5 67.49,20.5 67.67,20.68 67.67,20.86 67.53,21 67.53,21.18 67.71,21.36 67.89,21.36 68.03,21.22 68.21,21.22 68.39,21.4 68.39,21.58 68.25,21.72 68.25,21.9 68.43,22.08 68.61,22.08 68.75,21.94 68.93,21.94 69.11,22.12 69.11,22.3 68.97,22.44 68.97,22.62 69.15,22.8 69.33,22.8 69.47,22.66 69.65,22.66 69.83,22.84 69.83,23.02 69.69,23.15 69.69,23.33 69.87,23.51 70.05,23.51 70.19,23.38 70.37,23.38 70.55,23.56 70.55,23.74 70.41,23.87 70.41,24.05 70.59,24.23 70.77,24.23 70.91,24.1 71.09,24.1 71.34,24.35 71.34,24.53 71.2,24.66 71.2,24.84 71.38,25.02 71.56,25.02 71.7,24.89 71.88,24.89 72.26,25.27 72.26,25.5 72.13,25.63 71.88,25.63 71.75,25.76 71.75,26.01 71.88,26.14 72.26,26.14 72.39,26.27 72.39,26.52 72.26,26.65 71.88,26.65 71.75,26.77 71.75,27.03 71.88,27.16 72.26,27.16 72.39,27.28 72.39,27.54 72.26,27.66 71.88,27.66 71.75,27.79 71.75,28.04 71.88,28.17 72.26,28.17 72.39,28.3 72.39,28.55 72.26,28.68 71.88,28.68 71.75,28.81 71.75,29.06 71.88,29.19 72.26,29.19 72.39,29.31 72.39,29.57 72.26,29.7 71.88,29.7 71.75,29.82 71.75,30.08 71.88,30.2 72.26,30.2 72.39,30.33 72.39,30.58 72.26,30.71 71.88,30.71 71.75,30.84 71.75,31.09 71.88,31.22 72.26,31.22 72.39,31.35 72.39,31.6 72.26,31.73 71.88,31.73 71.75,31.85 71.75,32.13 86.87,47.24 87.18,47.24 87.3,47.37 87.3,47.62 87.43,47.75 87.68,47.75 87.81,47.62 87.81,47.37 87.94,47.24 88.75,47.24 88.87,47.37 88.87,47.65 88.5,48.03 88.14,48.03 88.01,48.15 88.01,48.41 88.14,48.54 88.52,48.54 88.65,48.66 88.65,49.02 89.31,49.68 v1(89.66,49.68)
VOUT1_D4: length 91.9
  TOP w0.127: v1(90.49,50.18) U16.59 ; J14.54 v1(47.01,5.59)
  INNER1 w0.127: v1(47.01,5.59) 47.31,5.88 47.31,6.31 47.43,6.44 48.49,6.44 48.61,6.31 48.61,5.71 48.74,5.59 49,5.59 49.12,5.71 49.12,6.31 49.25,6.44 49.52,6.44 49.65,6.31 49.65,6.16 49.78,6.03 50.03,6.03 50.16,6.16 50.16,6.31 50.28,6.44 50.48,6.44 50.61,6.57 50.61,6.82 50.48,6.95 47.43,6.95 47.31,7.08 47.31,7.94 48.13,8.76 48.13,10.6 48.01,10.72 47.75,10.72 47.62,10.85 47.62,11.11 47.75,11.23 48.01,11.23 48.13,11.36 48.13,11.68 50.55,14.1 55.69,14.1 56.17,14.57 56.35,14.57 56.77,14.15 56.95,14.15 57.13,14.33 57.13,14.51 56.71,14.93 56.71,15.11 56.89,15.29 57.06,15.29 57.49,14.87 57.67,14.87 57.85,15.05 57.85,15.23 57.42,15.65 57.42,15.83 57.6,16.01 57.78,16.01 58.21,15.59 58.39,15.59 58.57,15.77 58.57,15.95 58.14,16.37 58.14,16.55 58.32,16.73 58.5,16.73 58.93,16.31 59.11,16.31 59.29,16.49 59.29,16.67 58.86,17.09 58.86,17.27 59.04,17.45 59.22,17.45 59.64,17.03 59.82,17.03 60,17.21 60,17.39 59.58,17.81 59.58,17.99 59.76,18.17 59.94,18.17 60.36,17.74 60.54,17.74 60.72,17.92 60.72,18.1 60.3,18.53 60.3,18.71 60.71,19.11 61.01,19.11 61.14,18.99 61.14,18.54 61.26,18.41 61.52,18.41 61.65,18.54 61.65,18.99 61.77,19.11 63.82,19.11 64.07,19.37 64.39,19.37 64.58,19.18 64.9,19.18 71.25,25.53 71.25,30.83 71.12,30.95 70.61,30.95 70.48,31.08 70.48,31.34 70.61,31.46 71.12,31.46 71.25,31.59 71.25,32.26 89.17,50.18 v1(90.49,50.18)
VOUT1_D5: length 92
  TOP w0.127: U16.58 91.74,50.67 v1(89.66,50.67) ; J14.52 v1(46.51,4.83)
  INNER1 w0.127: v1(89.66,50.67) 89.03,50.67 69.98,31.62 69.98,31.36 69.85,31.23 69.6,31.23 69.47,31.1 69.47,30.85 69.6,30.72 69.85,30.72 69.98,30.59 69.98,30.46 70.1,30.33 70.61,30.33 70.74,30.2 70.74,29.95 70.61,29.82 70.1,29.82 69.98,29.69 69.98,29.44 70.1,29.31 70.61,29.31 70.74,29.19 70.74,28.3 70.61,28.17 70.38,28.17 70.14,28.41 69.81,28.41 69.57,28.17 69.34,28.17 69.22,28.04 69.22,27.79 69.34,27.66 70.61,27.66 70.74,27.53 70.74,27.28 70.61,27.15 70.1,27.15 69.98,27.03 69.98,26.77 70.1,26.65 70.61,26.65 70.74,26.52 70.74,26.26 70.61,26.14 69.83,26.14 69.69,26 69.69,25.77 70.18,25.28 70.18,25.1 70,24.92 69.82,24.92 69.5,25.25 69.32,25.25 69.14,25.07 69.14,24.89 69.47,24.56 69.47,24.38 69.29,24.2 69.11,24.2 68.78,24.53 68.6,24.53 68.42,24.35 68.42,24.17 68.75,23.84 68.75,23.66 68.57,23.48 68.39,23.48 68.06,23.81 67.88,23.81 67.7,23.63 67.7,23.45 68.03,23.12 68.03,22.94 67.85,22.76 67.67,22.76 67.34,23.09 67.16,23.09 66.98,22.91 66.98,22.73 67.31,22.4 67.31,22.22 67.13,22.04 66.95,22.04 66.62,22.37 66.44,22.37 66.26,22.19 66.26,22.01 66.59,21.68 66.59,21.51 66.41,21.33 66.23,21.33 65.9,21.65 65.72,21.65 65.54,21.47 65.54,21.29 65.87,20.97 65.87,20.79 65.69,20.61 65.51,20.61 65.18,20.94 65,20.94 64.82,20.75 64.82,20.58 65.15,20.25 65.15,20.07 64.97,19.89 64.79,19.89 64.02,20.66 63.84,20.66 63.66,20.48 63.66,20.3 63.93,20.04 63.93,19.86 63.63,19.56 60.58,19.56 55.5,14.48 50.42,14.48 47.12,11.18 47.12,10.44 47.24,10.31 47.56,10.31 47.69,10.18 47.69,9.93 47.56,9.8 47.24,9.8 47.12,9.67 47.12,9.42 47.24,9.29 47.56,9.29 47.69,9.17 47.69,8.91 47.56,8.79 47.05,8.79 46.93,8.66 46.93,7.18 46.55,6.79 46.55,6.54 46.74,6.35 46.74,6.1 46.51,5.87 v1(46.51,4.83)
VOUT1_D6: length 92.3
  TOP w0.127: J14.35 42.51,8.54 43.64,7.42 v1(46.42,7.42) ; v1(89.66,52.18) U16.55
  INNER1 w0.127: v1(46.42,7.42) 46.42,8.57 46.02,8.97 46.02,9.33 46.15,9.46 46.48,9.46 46.61,9.59 46.61,10.16 46.48,10.28 46.15,10.28 46.02,10.41 46.02,11.11 50.15,15.24 54.99,15.24 61.09,21.34 61.09,21.54 v1(61.39,21.84) 62.06,22.51 62.06,22.69 61.45,23.3 61.45,23.47 61.63,23.65 61.81,23.65 62.52,22.95 62.7,22.95 62.88,23.13 62.88,23.31 62.29,23.89 62.29,24.07 62.47,24.25 62.65,24.25 63.24,23.66 63.42,23.66 63.59,23.84 63.59,24.02 63.01,24.61 63.01,24.79 63.19,24.97 63.37,24.97 63.95,24.38 64.13,24.38 64.31,24.56 64.31,24.74 64.11,24.94 64.11,25.12 64.3,25.31 64.48,25.31 64.68,25.11 64.86,25.11 65.04,25.29 65.04,25.47 64.84,25.67 64.84,25.85 65.02,26.03 65.2,26.03 65.4,25.83 65.58,25.83 65.76,26.01 65.76,26.19 65.56,26.39 65.56,26.57 65.74,26.75 65.92,26.75 66.12,26.55 66.3,26.55 66.48,26.73 66.48,26.91 66.28,27.11 66.28,27.29 66.35,27.36 66.35,27.54 66.02,27.86 66.02,28.04 66.2,28.22 66.38,28.22 66.59,28.01 67.04,27.56 67.31,27.56 68.2,28.45 68.2,29.92 68.07,30.04 67.06,30.04 66.93,30.17 66.93,30.42 67.06,30.55 68.07,30.55 68.2,30.68 68.2,31.31 68.07,31.44 68.07,31.62 68.25,31.8 68.43,31.8 68.57,31.66 68.75,31.66 68.93,31.84 68.93,32.02 68.79,32.16 68.79,32.34 68.97,32.52 69.15,32.52 69.29,32.38 69.47,32.38 69.65,32.56 69.65,32.74 69.51,32.88 69.51,33.06 69.69,33.24 69.87,33.24 70.01,33.1 70.19,33.1 70.36,33.28 70.36,33.46 70.23,33.6 70.23,33.78 70.41,33.96 70.59,33.96 70.72,33.82 70.9,33.82 71.08,34 71.08,34.18 70.95,34.32 70.95,34.5 71.13,34.68 71.31,34.68 71.44,34.54 71.62,34.54 71.8,34.72 71.8,34.9 71.66,35.04 71.66,35.22 71.84,35.4 72.02,35.4 72.16,35.26 72.34,35.26 89.27,52.18 v1(89.66,52.18)
  BOTTOM w0.127: v1(61.39,21.84) 61.39,21.85 J13.13
VOUT1_D7: length 92.9
  TOP w0.127: U16.54 v1(90.49,52.68) ; J14.50 v1(46.01,5.59)
  INNER1 w0.127: v1(46.01,5.59) 46.01,7.12 45.71,7.43 45.71,7.88 45.81,7.98 45.94,7.98 46.04,8.08 46.04,8.29 45.94,8.39 45.81,8.39 45.71,8.49 45.71,11.3 50.03,15.62 54.8,15.62 60.39,21.21 v1(60.39,21.84) 60.9,22.35 60.9,22.66 60.77,22.79 60.64,22.79 60.52,22.91 60.52,23.17 60.64,23.29 60.77,23.29 60.9,23.42 60.9,23.67 60.77,23.8 60.64,23.8 60.52,23.93 60.52,24.18 60.64,24.31 61.27,24.31 61.59,24.64 61.59,25.78 61.85,26.04 62.17,26.04 62.29,25.91 62.29,25.65 62.42,25.53 62.67,25.53 62.8,25.65 62.8,25.91 62.93,26.04 63.18,26.04 63.31,25.91 63.31,25.65 63.44,25.53 63.69,25.53 63.82,25.65 63.82,25.91 63.94,26.04 64.39,26.04 65.53,27.18 65.53,28.7 66.23,29.4 66.23,30.42 71.93,36.12 72.11,36.12 72.25,35.98 72.43,35.98 72.61,36.16 72.61,36.34 72.47,36.48 72.47,36.66 72.65,36.84 72.83,36.84 72.97,36.7 73.15,36.7 73.33,36.88 73.33,37.06 73.19,37.2 73.19,37.38 73.37,37.56 73.55,37.56 73.69,37.42 73.87,37.42 74.05,37.6 74.05,37.78 73.91,37.92 73.91,38.1 74.09,38.27 74.27,38.27 74.41,38.14 74.59,38.14 74.77,38.32 74.77,38.5 74.63,38.63 74.63,38.81 74.81,38.99 74.99,38.99 75.13,38.86 75.3,38.86 75.48,39.04 75.48,39.22 75.35,39.35 75.35,39.53 75.53,39.71 75.71,39.71 75.84,39.57 76.02,39.57 76.2,39.75 76.2,39.93 76.07,40.07 76.07,40.25 76.25,40.43 76.43,40.43 76.56,40.29 76.74,40.29 76.92,40.47 76.92,40.65 76.78,40.79 76.78,40.97 76.96,41.15 77.14,41.15 77.28,41.01 77.46,41.01 77.64,41.19 77.64,41.37 77.5,41.51 77.5,41.69 77.68,41.87 77.86,41.87 78,41.73 78.18,41.73 78.36,41.91 78.36,42.09 78.22,42.23 78.22,42.41 78.4,42.59 78.58,42.59 78.72,42.45 78.9,42.45 79.08,42.63 79.08,42.81 78.94,42.95 78.94,43.13 79.12,43.31 79.3,43.31 79.44,43.17 79.62,43.17 79.8,43.35 79.8,43.53 79.66,43.67 79.66,43.85 79.84,44.03 80.02,44.03 80.16,43.89 80.34,43.89 80.52,44.07 80.52,44.25 80.38,44.38 80.38,44.56 80.56,44.74 80.74,44.74 80.88,44.61 81.06,44.61 81.24,44.79 81.24,44.97 81.1,45.1 81.1,45.28 81.28,45.46 81.46,45.46 81.59,45.33 81.77,45.33 81.95,45.5 81.95,45.68 81.82,45.82 81.82,46 82,46.18 82.18,46.18 82.31,46.04 82.49,46.04 82.67,46.22 82.67,46.4 82.54,46.54 82.54,46.72 82.71,46.9 82.89,46.9 83.03,46.76 83.21,46.76 83.39,46.94 83.39,47.12 83.25,47.26 83.25,47.44 83.43,47.62 83.61,47.62 83.75,47.48 83.93,47.48 84.11,47.66 84.11,47.84 83.97,47.98 83.97,48.16 84.15,48.34 84.33,48.34 84.47,48.2 84.65,48.2 84.83,48.38 84.83,48.56 84.69,48.7 84.69,48.88 84.87,49.06 85.05,49.06 85.19,48.92 85.37,48.92 85.55,49.1 85.55,49.28 85.41,49.42 85.41,49.6 85.59,49.78 85.77,49.78 85.91,49.64 86.09,49.64 86.27,49.82 86.27,50 86.13,50.14 86.13,50.32 86.31,50.49 86.49,50.49 86.63,50.36 86.81,50.36 86.99,50.54 86.99,50.72 86.85,50.85 86.85,51.03 87.03,51.21 87.21,51.21 87.35,51.08 87.52,51.08 87.7,51.26 87.7,51.44 87.57,51.57 87.57,51.75 87.75,51.93 87.93,51.93 88.06,51.79 88.24,51.79 88.42,51.97 88.42,52.15 88.29,52.29 88.29,52.47 88.5,52.68 v1(90.49,52.68)
  BOTTOM w0.127: v1(60.39,21.84) J13.17
VOUT1_D8: length 92.5
  TOP w0.127: J14.48 v1(45.51,4.83) ; v1(89.66,53.19) 91.75,53.19 U16.53
  INNER1 w0.127: v1(89.66,53.19) 88.37,53.19 72.59,37.41 72.41,37.41 72.14,37.67 71.96,37.67 71.78,37.49 71.78,37.31 72.05,37.05 72.05,36.87 71.87,36.69 71.69,36.69 71.42,36.95 71.24,36.95 71.07,36.78 71.07,36.6 71.33,36.33 71.33,36.15 71.15,35.97 70.97,35.97 70.71,36.24 70.53,36.24 70.35,36.06 70.35,35.88 70.61,35.61 70.61,35.43 70.43,35.25 70.25,35.25 69.99,35.52 69.81,35.52 69.63,35.34 69.63,35.16 69.89,34.89 69.89,34.71 69.71,34.53 69.53,34.53 69.27,34.8 69.09,34.8 68.91,34.62 68.91,34.44 69.17,34.17 69.17,33.99 68.99,33.81 68.81,33.81 68.55,34.08 68.37,34.08 68.19,33.9 68.19,33.72 68.45,33.46 68.45,33.28 68.27,33.1 68.1,33.1 67.83,33.36 67.65,33.36 67.47,33.18 67.47,33 67.74,32.74 67.74,32.56 67.56,32.38 67.38,32.38 67.11,32.64 66.93,32.64 66.75,32.46 66.75,32.28 67.02,32.02 67.02,31.84 66.84,31.66 66.66,31.66 66.39,31.92 66.21,31.92 66.03,31.74 66.03,31.56 66.3,31.3 66.3,31.12 65.79,30.61 65.79,29.59 65.02,28.83 65.02,27.3 64.26,26.54 62.72,26.54 62.59,26.67 62.59,27.05 62.46,27.18 62.21,27.18 62.08,27.05 62.08,26.67 61.95,26.54 60.96,26.54 59.82,25.4 58.76,25.4 58.64,25.27 v1(58.64,24.99) 58.97,24.66 59.94,24.66 60.04,24.56 60.04,24.29 59.94,24.19 59.27,24.19 59.17,24.09 59.17,23.82 59.27,23.72 59.94,23.72 60.04,23.62 60.04,23.35 59.94,23.25 59.27,23.25 59.17,23.15 59.17,22.88 59.27,22.78 59.94,22.78 60.04,22.68 60.04,22.41 59.94,22.31 59.27,22.31 59.17,22.21 59.17,20.56 54.61,16 49.9,16 45.39,11.49 45.39,7.11 45.51,6.99 v1(45.51,4.83)
  BOTTOM w0.127: J13.23 58.89,24.74 v1(58.64,24.99)
VOUT1_D9: length 92
  TOP w0.127: U16.52 v1(90.49,53.68) ; J14.46 v1(45.01,5.59)
  INNER1 w0.127: v1(45.01,5.59) 45.01,7.05 45.07,7.11 45.07,11.68 49.77,16.38 54.42,16.38 58.64,20.6 v1(58.64,21.79) 58.64,24.04 58.17,24.51 58.17,26.04 58.35,26.22 58.53,26.22 58.73,26.01 58.91,26.01 59.09,26.19 59.09,26.37 58.89,26.57 58.89,26.75 59.51,27.38 59.69,27.38 60.34,26.73 60.52,26.73 60.7,26.91 60.7,27.09 60.05,27.74 60.05,27.92 60.33,28.19 60.58,28.19 60.8,27.98 61.09,27.98 61.31,28.19 63.25,28.19 63.5,27.94 63.82,27.94 64.52,28.64 64.52,28.96 65.34,29.78 65.34,31.69 72.06,38.4 72.24,38.4 72.5,38.14 72.68,38.14 72.86,38.32 72.86,38.5 72.6,38.76 72.6,38.94 72.78,39.12 72.96,39.12 73.22,38.86 73.4,38.86 73.58,39.04 73.58,39.22 73.32,39.48 73.32,39.66 73.5,39.84 73.68,39.84 73.94,39.58 74.12,39.58 74.3,39.76 74.3,39.94 74.04,40.2 74.04,40.38 74.22,40.56 74.4,40.56 74.66,40.3 74.84,40.3 75.02,40.48 75.02,40.65 74.75,40.92 74.75,41.1 74.93,41.28 75.11,41.28 75.38,41.01 75.56,41.01 75.74,41.19 75.74,41.37 75.47,41.64 75.47,41.82 75.65,42 75.83,42 76.1,41.73 76.28,41.73 76.46,41.91 76.46,42.09 76.19,42.36 76.19,42.54 76.37,42.72 76.55,42.72 76.82,42.45 77,42.45 77.18,42.63 77.18,42.81 76.91,43.08 76.91,43.26 77.09,43.44 77.27,43.44 77.54,43.17 77.71,43.17 77.89,43.35 77.89,43.53 77.63,43.79 77.63,43.97 77.81,44.15 77.99,44.15 78.25,43.89 78.43,43.89 78.61,44.07 78.61,44.25 78.35,44.51 78.35,44.69 78.53,44.87 78.71,44.87 78.97,44.61 79.15,44.61 79.33,44.79 79.33,44.97 79.07,45.23 79.07,45.41 79.25,45.6 79.43,45.6 79.69,45.34 79.88,45.34 88.23,53.68 v1(90.49,53.68)
  BOTTOM w0.127: J13.25 58.39,22.04 v1(58.64,21.79)
VOUT1_D10: length 92.5
  TOP w0.127: J14.44 v1(44.51,4.83) ; U16.51 v1(89.66,54.18)
  INNER1 w0.127: v1(89.66,54.18) 88.09,54.18 85.22,51.31 84.71,51.31 84.58,51.18 84.58,50.67 84.45,50.55 84.2,50.55 84.07,50.67 84.07,51.18 83.95,51.31 83.69,51.31 83.12,50.73 83.12,50.55 83.7,49.97 83.7,49.79 83.52,49.61 83.34,49.61 82.76,50.2 82.58,50.2 82.4,50.02 82.4,49.84 82.98,49.25 82.98,49.07 82.8,48.89 82.62,48.89 82.04,49.48 81.86,49.48 81.68,49.3 81.68,49.12 82.26,48.54 82.26,48.36 82.08,48.18 81.9,48.18 81.32,48.76 81.14,48.76 80.96,48.58 80.96,48.4 81.55,47.82 81.55,47.64 81.37,47.46 81.19,47.46 80.6,48.04 80.42,48.04 80.24,47.86 80.24,47.68 80.83,47.1 80.83,46.92 80.65,46.74 80.47,46.74 79.89,47.32 79.71,47.32 79.53,47.14 79.53,46.96 80.11,46.38 80.11,46.2 79.93,46.02 79.75,46.02 79.17,46.6 78.99,46.6 78.81,46.42 78.81,46.24 78.94,46.1 78.94,45.92 64.9,31.88 64.9,29.97 63.5,28.57 60.07,28.57 57.64,26.14 v1(57.64,24.99) 57.64,24.46 58.15,23.94 58.15,20.69 54.23,16.76 49.64,16.76 44.75,11.87 44.75,7.43 44.51,7.19 v1(44.51,4.83)
  BOTTOM w0.127: v1(57.64,24.99) 57.89,24.74 J13.27
VOUT1_D11: length 93.5
  TOP w0.127: J14.42 v1(44.01,5.59) ; U16.50 v1(90.49,54.68)
  INNER1 w0.127: v1(44.01,5.59) 44.01,7.26 44.44,7.68 44.44,12.06 49.52,17.14 54.04,17.14 57.64,20.74 v1(57.64,21.79) 57.64,23.77 57.15,24.26 57.15,26.29 59.82,28.96 63.25,28.96 64.45,30.16 64.45,32.07 67.42,35.03 67.42,35.21 67.28,35.35 67.28,35.53 67.46,35.71 67.64,35.71 67.78,35.57 67.96,35.57 68.14,35.75 68.14,35.93 68,36.07 68,36.25 68.18,36.43 68.36,36.43 68.5,36.29 68.68,36.29 68.86,36.47 68.86,36.65 68.72,36.79 68.72,36.97 68.9,37.15 69.08,37.15 69.22,37.01 69.4,37.01 69.58,37.19 69.58,37.37 69.44,37.51 69.44,37.69 69.62,37.87 69.8,37.87 69.94,37.73 70.12,37.73 70.3,37.91 70.3,38.09 70.16,38.23 70.16,38.41 70.34,38.59 70.52,38.59 70.65,38.45 70.83,38.45 71.01,38.63 71.01,38.81 70.88,38.95 70.88,39.13 71.06,39.31 71.24,39.31 71.37,39.17 71.55,39.17 71.73,39.35 71.73,39.53 71.59,39.67 71.59,39.84 71.77,40.02 71.95,40.02 72.09,39.89 72.27,39.89 72.45,40.07 72.45,40.25 72.31,40.38 72.31,40.56 72.49,40.74 72.67,40.74 72.81,40.61 72.99,40.61 73.17,40.79 73.17,40.97 73.03,41.1 73.03,41.28 73.21,41.46 73.39,41.46 73.53,41.32 73.71,41.32 73.89,41.5 73.89,41.68 73.75,41.82 73.75,42 73.93,42.18 74.11,42.18 74.25,42.04 74.43,42.04 74.61,42.22 74.61,42.4 74.47,42.54 74.47,42.72 74.65,42.9 74.83,42.9 74.97,42.76 75.15,42.76 75.33,42.94 75.33,43.12 75.19,43.26 75.19,43.44 75.37,43.62 75.55,43.62 75.69,43.48 75.87,43.48 76.05,43.66 76.05,43.84 75.91,43.98 75.91,44.16 76.09,44.34 76.27,44.34 76.4,44.2 76.58,44.2 76.76,44.38 76.76,44.56 76.63,44.7 76.63,44.88 76.81,45.06 76.99,45.06 77.12,44.92 77.3,44.92 77.48,45.1 77.48,45.28 77.35,45.42 77.35,45.6 77.53,45.78 77.7,45.78 77.84,45.64 78.02,45.64 78.2,45.82 78.2,46 78.06,46.13 78.06,46.31 83.5,51.75 85.03,51.75 89.66,56.39 90.3,56.39 90.49,56.2 90.49,55.94 90.36,55.82 89.79,55.82 89.66,55.69 89.66,55.44 89.79,55.31 90.36,55.31 90.49,55.18 v1(90.49,54.68)
  BOTTOM w0.127: J13.29 57.39,22.04 v1(57.64,21.79)
VOUT1_D12: length 92.9
  TOP w0.127: v1(94.25,58.42) U16.47 ; J14.40 v1(43.51,4.83)
  INNER1 w0.127: v1(43.51,4.83) 43.51,7.33 44.12,7.94 44.12,12.26 49.39,17.53 53.85,17.53 57.15,20.83 57.15,23.67 56.64,24.19 v1(56.64,24.99) 56.64,26.41 59.56,29.34 62.99,29.34 64.01,30.35 64.01,31.09 63.88,31.22 63.5,31.22 63.37,31.34 63.37,31.6 63.5,31.72 63.88,31.72 64.01,31.85 64.01,32.26 66.67,34.92 66.67,35.56 83.31,52.2 84.84,52.2 90.17,57.53 90.63,57.53 90.76,57.4 90.76,56.77 90.89,56.64 91.14,56.64 91.27,56.77 91.27,57.4 91.39,57.53 91.65,57.53 91.78,57.4 91.78,56.77 91.9,56.64 92.16,56.64 92.28,56.77 92.28,57.4 92.41,57.53 93.44,57.53 93.56,57.4 93.56,56.77 93.69,56.64 93.95,56.64 94.07,56.77 94.07,57.4 94.2,57.53 94.49,57.53 94.61,57.66 94.61,58.06 v1(94.25,58.42)
  BOTTOM w0.127: J13.31 56.89,24.74 v1(56.64,24.99)
VOUT1_D13: length 91.6
  TOP w0.127: U16.46 94.74,57.19 94.74,58.93 94.23,59.44 93.09,59.44 v1(91.82,58.17) ; J14.38 v1(43.01,5.59)
  INNER1 w0.127: v1(91.82,58.17) 89.15,58.17 88.65,57.66 88.65,56.64 84.65,52.64 83.12,52.64 66.17,35.69 66.17,35.05 62.61,31.5 62.61,30.35 61.98,29.72 58.55,29.72 58.35,29.52 58.35,29.34 58.55,29.14 58.55,28.96 58.37,28.78 58.19,28.78 57.99,28.98 57.81,28.98 57.63,28.8 57.63,28.62 57.83,28.42 57.83,28.24 57.65,28.06 57.47,28.06 57.27,28.26 57.09,28.26 56.91,28.08 56.91,27.9 57.11,27.7 57.11,27.52 56.93,27.34 56.75,27.34 56.55,27.54 56.37,27.54 56.18,27.36 56.18,24.08 56.64,23.63 v1(56.64,21.79) 56.64,20.89 53.66,17.91 49.26,17.91 43.8,12.45 43.8,8.13 43.01,7.34 v1(43.01,5.59)
  BOTTOM w0.127: J13.33 56.39,22.04 v1(56.64,21.79)
VOUT1_D14: length 92.5
  TOP w0.127: U16.45 v1(95.25,58.42) ; J14.36 v1(42.51,4.83)
  INNER1 w0.127: v1(42.51,4.83) 42.51,7.41 43.48,8.38 43.48,12.64 49.14,18.29 53.47,18.29 56.13,20.95 56.13,23.42 55.64,23.92 v1(55.64,24.99) 55.64,27.44 58.29,30.1 58.59,30.1 58.72,30.23 58.72,30.45 58.84,30.58 59.1,30.58 59.23,30.45 59.23,30.23 59.35,30.1 59.61,30.1 59.73,30.23 59.73,30.61 59.86,30.73 60.11,30.73 60.24,30.61 60.24,30.23 60.37,30.1 61.15,30.1 61.39,30.34 61.39,30.91 65.66,35.18 65.66,35.81 82.93,53.09 84.2,53.09 87,55.88 87,57.15 87.5,57.66 87.68,57.66 87.82,57.52 88,57.52 88.18,57.7 88.18,57.88 88.04,58.02 88.04,58.2 88.77,58.93 89.13,58.93 89.33,58.74 89.71,58.74 89.9,58.93 90.28,58.93 90.47,58.74 90.85,58.74 91.04,58.93 92.09,58.93 92.22,58.8 92.22,58.67 92.34,58.55 92.53,58.55 92.66,58.67 92.66,58.8 92.79,58.93 94.74,58.93 v1(95.25,58.42)
  BOTTOM w0.127: J13.35 55.89,24.74 v1(55.64,24.99)
VOUT1_D15: length 93
  TOP w0.127: J14.34 v1(42.01,5.59) ; U16.44 v1(95.75,59.18)
  INNER1 w0.127: v1(42.01,5.59) 42.01,7.48 43.17,8.64 43.17,12.83 49.01,18.67 53.28,18.67 55.64,21.03 v1(55.64,21.79) 55.64,23.28 55.14,23.77 55.14,27.58 58.8,31.24 61.09,31.24 65.15,35.31 65.15,35.94 82.74,53.53 83.76,53.53 84.71,54.48 84.71,55.5 84.96,55.75 85.14,55.75 85.46,55.42 85.64,55.42 85.82,55.6 85.82,55.78 85.49,56.11 85.49,56.28 85.67,56.46 85.85,56.46 86.18,56.14 86.36,56.14 86.54,56.32 86.54,56.5 86.21,56.82 86.21,57 88.52,59.31 95.12,59.31 95.25,59.18 v1(95.75,59.18)
  BOTTOM w0.127: J13.37 55.39,22.04 v1(55.64,21.79)
VOUT1_D16: length 91.7
  TOP w0.127: U16.43 v1(96.25,58.42) ; J14.31 41.51,8.74 v1(42.01,8.24)
  INNER1 w0.127: v1(96.25,58.42) 96.25,59.45 96.01,59.69 88.27,59.69 84.26,55.69 84.26,54.67 83.57,53.98 82.55,53.98 64.58,36 64.58,35.82 64.71,35.68 64.71,35.5 64.53,35.32 64.35,35.32 64.22,35.46 64.04,35.46 63.86,35.28 63.86,35.1 63.99,34.96 63.99,34.78 63.81,34.6 63.63,34.6 63.5,34.74 63.32,34.74 63.14,34.56 63.14,34.38 63.28,34.25 63.28,34.07 63.1,33.89 62.92,33.89 62.78,34.02 62.6,34.02 62.42,33.84 62.42,33.66 62.56,33.53 62.56,33.35 62.38,33.17 62.2,33.17 62.06,33.3 61.88,33.3 61.59,33.02 61.59,32.38 60.9,31.69 58.61,31.69 54.64,27.71 v1(54.64,24.99) 54.64,23.65 55.14,23.14 55.14,21.11 53.09,19.05 48.88,19.05 42.85,13.02 42.85,9.08 v1(42.01,8.24)
  BOTTOM w0.127: v1(54.64,24.99) 54.89,24.74 J13.39
VOUT1_D17: length 93.5
  TOP w0.127: J14.32 v1(41.51,4.83) ; U16.42 v1(96.75,59.18)
  INNER1 w0.127: v1(96.75,59.18) 96.75,59.59 96.27,60.07 88.01,60.07 83.82,55.88 83.82,54.86 83.38,54.42 82.36,54.42 61.15,33.21 61.15,32.58 60.71,32.13 58.42,32.13 54.1,27.81 54.1,23.5 54.64,22.96 v1(54.64,21.79) 54.64,21.17 52.9,19.43 48.76,19.43 42.53,13.21 42.53,9.59 41.51,8.57 v1(41.51,4.83)
  BOTTOM w0.127: J13.41 54.39,22.04 v1(54.64,21.79)
VOUT1_D18: length 92.7
  TOP w0.127: U16.41 v1(97.25,58.42) ; J14.33 v1(42.01,10.87)
  INNER1 w0.127: v1(42.01,10.87) 42.15,11.01 42.15,13.34 48.63,19.81 52.7,19.81 54.13,21.23 54.13,22.89 53.64,23.38 v1(53.64,24.99) 53.64,29.13 53.82,29.31 54,29.31 54.39,28.91 54.57,28.91 54.75,29.09 54.75,29.27 54.36,29.67 54.36,29.85 54.54,30.03 54.72,30.03 55.11,29.63 55.29,29.63 55.47,29.81 55.47,29.99 55.08,30.38 55.08,30.56 55.25,30.74 55.43,30.74 55.83,30.35 56.01,30.35 56.19,30.53 56.19,30.71 55.79,31.1 55.79,31.28 55.98,31.47 56.16,31.47 56.49,31.14 56.8,31.14 58.23,32.58 58.23,33.21 58.67,33.66 60.96,33.66 87.76,60.45 96.52,60.45 97.25,59.72 v1(97.25,58.42)
  BOTTOM w0.127: J13.43 53.89,24.74 v1(53.64,24.99)
VOUT1_D19: length 96.5
  TOP w0.127: U16.40 v1(97.75,59.18) ; J14.30 v1(41.01,5.59)
  INNER1 w0.127: v1(97.75,59.18) 97.75,59.86 96.77,60.83 87.5,60.83 60.77,34.1 56.96,34.1 56.13,33.27 56.13,32.38 53.14,29.39 53.14,23.24 53.64,22.74 v1(53.64,21.79) 53.64,21.32 52.51,20.19 48.5,20.19 41.77,13.46 41.77,11.34 41.01,10.58 v1(41.01,5.59)
  BOTTOM w0.127: v1(53.64,21.79) 53.39,22.04 J13.45
VOUT1_D20: length 91.5
  TOP w0.127: J14.29 v1(41.01,11.29) ; U16.39 v1(98.25,58.42)
  INNER1 w0.127: v1(98.25,58.42) 98.25,59.99 97.03,61.21 87.25,61.21 60.58,34.54 56.77,34.54 55.63,33.4 55.63,32.64 52.64,29.65 v1(52.64,24.99) 52.64,23.11 53.14,22.61 53.14,21.39 52.32,20.57 48.37,20.57 41.45,13.65 41.45,11.76 41.01,11.32 v1(41.01,11.29)
  BOTTOM w0.127: v1(52.64,24.99) 52.89,24.74 J13.47
VOUT1_D21: length 93.1
  TOP w0.127: U16.38 v1(98.75,59.18) ; J14.27 40.51,11.51 v1(41.01,12.01)
  INNER1 w0.127: v1(98.75,59.18) 98.75,60.13 97.28,61.59 87,61.59 60.39,34.99 56.32,34.99 54.61,33.27 54.61,32.38 52.2,29.97 52.2,22.99 52.64,22.55 v1(52.64,21.79) 52.64,21.46 52.13,20.95 48.25,20.95 41.01,13.72 v1(41.01,12.01)
  BOTTOM w0.127: J13.49 52.39,22.04 v1(52.64,21.79)
VOUT1_D22: length 100.8
  TOP w0.127: U16.37 v1(99.25,58.42) ; J14.28 v1(40.51,4.83)
  INNER1 w0.127: v1(40.51,4.83) 40.51,13.73 48.12,21.34 51.94,21.34 52.12,21.51 52.12,22.42 51.64,22.9 v1(51.64,24.99) 51.64,31.44 55.63,35.43 60.2,35.43 86.74,61.98 97.54,61.98 99.25,60.26 v1(99.25,58.42)
  BOTTOM w0.127: v1(51.64,24.99) 51.89,24.74 J13.51
